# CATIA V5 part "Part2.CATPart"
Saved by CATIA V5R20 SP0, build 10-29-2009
Part number: Part2
Bounding box of the stored display mesh (mm): x -75 to 75, y -50 to 50, z 0 to 5
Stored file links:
  C:\Users\Lenovo\Desktop\存钱\Part2.CATPart
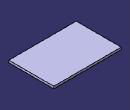
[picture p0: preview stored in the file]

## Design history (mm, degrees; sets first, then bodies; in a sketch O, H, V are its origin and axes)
Body1 (main body)
  Sketch1 on xy-plane, origin (0, 0, 0), H (1, 0, 0), V (0, 1, 0)
    line L1 (75, 50) -> (75, -50)
    line L2 (75, -50) -> (-75, -50)
    line L3 (-75, -50) -> (-75, 50)
    line L4 (-75, 50) -> (75, 50)
    length L4 = 150
    length L1 = 100
    vertical: L1 V, L3 V
    horizontal: L2 H, L4 H
    equidistance: L1 L3 O, L2 L4 O
  Pad1: profile Sketch1, direction (0, 0, 1), length 5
